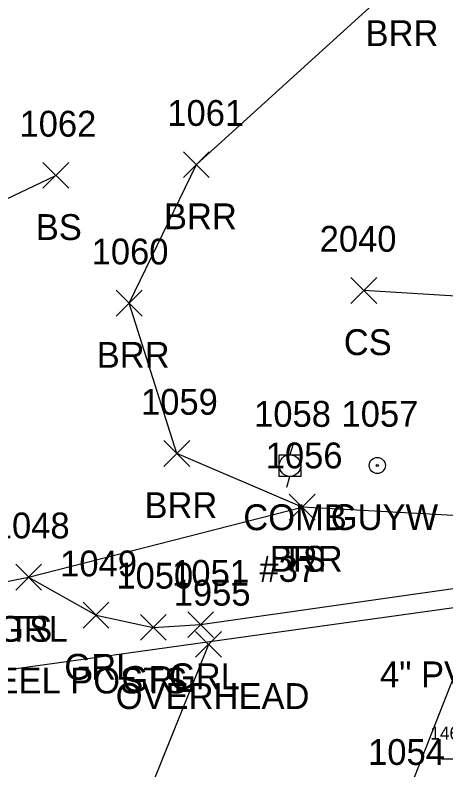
# Model space of a CAD drawing. Extents: x 1600395 to 1603269, y 874955 to 877143.
# Drawn here: x 1601724 to 1601757.4, y 875237.1 to 875295.5 of the extents above; entities that cross this region are included whole.
import ezdxf

# ---------------------------------------------------------------- set-up
doc = ezdxf.new("R2010")
doc.units = 0
for name, color, linetype in [('B_I', 7, 'Continuous'), ('B_TIC', 7, 'Continuous'), ('L_A', 7, 'Continuous'), ('L_I', 7, 'Continuous'), ('L_TIC', 7, 'Continuous'), ('LABL', 7, 'Continuous'), ('LELB', 7, 'Continuous'), ('P_I', 7, 'Continuous'), ('PET', 7, 'Continuous'), ('R_A', 7, 'Continuous'), ('R_C', 7, 'Continuous'), ('R_I', 7, 'Continuous'), ('R_TIC', 7, 'Continuous'), ('RGR', 7, 'Continuous'), ('U_A', 7, 'Continuous'), ('U_C', 7, 'Continuous'), ('U_I', 7, 'Continuous'), ('U_TIC', 7, 'Continuous'), ('UCO', 7, 'Continuous'), ('UP', 7, 'Continuous'), ('UPGW', 7, 'Continuous')]:
    doc.layers.add(name, color=color, linetype=linetype)

msp = doc.modelspace()

# ---------------------------------------------------------------- linework, layer by layer
at = {"layer": 'B_TIC'}
msp.add_lwpolyline([(1601757.063, 875237.938), (1601758.063, 875237.938)], dxfattribs=at)
at = {"layer": 'L_TIC'}
for points in [[(1601737.075, 875282.934), (1601739.075, 875284.934)], [(1601739.075, 875282.934), (1601737.075, 875284.934)], [(1601726.194, 875282.102), (1601728.194, 875284.102)], [(1601728.194, 875282.102), (1601726.194, 875284.102)], [(1601750.052, 875273.194), (1601752.052, 875275.194)], [(1601752.052, 875273.194), (1601750.052, 875275.194)], [(1601731.869, 875272.211), (1601733.869, 875274.211)], [(1601733.869, 875272.211), (1601731.869, 875274.211)], [(1601735.567, 875260.578), (1601737.567, 875262.578)], [(1601737.567, 875260.578), (1601735.567, 875262.578)], [(1601745.273, 875256.428), (1601747.273, 875258.428)], [(1601747.273, 875256.428), (1601745.273, 875258.428)], [(1601745.273, 875256.428), (1601747.273, 875258.428)], [(1601747.273, 875256.428), (1601745.273, 875258.428)], [(1601724.08, 875251.006), (1601726.08, 875253.006)], [(1601726.08, 875251.006), (1601724.08, 875253.006)]]:
    msp.add_lwpolyline(points, dxfattribs=at)
at = {"layer": 'LABL'}
msp.add_lwpolyline([(1601761.25, 875256.599), (1601746.273, 875257.428), (1601736.567, 875261.578), (1601732.869, 875273.211), (1601738.075, 875283.934), (1601753.692, 875298.112), (1601772.592, 875313.657), (1601797.68, 875329.997)], dxfattribs=at)
at = {"layer": 'LELB'}
for points in [[(1601507.847, 875247.89), (1601547.421, 875248.527), (1601578.347, 875245.47), (1601617.951, 875253.676), (1601656.941, 875253.767), (1601694.042, 875267.342), (1601727.194, 875283.102)], [(1601777.022, 875268.044), (1601766.132, 875273.264), (1601751.052, 875274.194)], [(1601507.321, 875231.194), (1601546.9, 875233.686), (1601579.202, 875234.27), (1601621.109, 875236.954), (1601658.665, 875241.356), (1601694.784, 875245.501), (1601700.77, 875248.817), (1601715.033, 875250.029), (1601725.08, 875252.006), (1601746.273, 875257.428)]]:
    msp.add_lwpolyline(points, dxfattribs=at)
at = {"layer": 'PET'}
msp.add_lwpolyline([(1601414.027, 875231.868), (1601447.658, 875227.337), (1601480.387, 875224.741), (1601507.332, 875223.944), (1601546.886, 875225.235), (1601579.482, 875227.318), (1601621.881, 875231.182), (1601659.141, 875235.732), (1601695.513, 875240.663), (1601718.889, 875244.213), (1601760.24, 875249.955), (1601754.149, 875234.472), (1601747.535, 875218.619)], dxfattribs=at)
at = {"layer": 'R_TIC'}
for points in [[(1601724.08, 875251.006), (1601726.08, 875253.006)], [(1601726.08, 875251.006), (1601724.08, 875253.006)], [(1601729.304, 875248.068), (1601731.304, 875250.068)], [(1601731.304, 875248.068), (1601729.304, 875250.068)], [(1601733.736, 875247.121), (1601735.736, 875249.121)], [(1601735.736, 875247.121), (1601733.736, 875249.121)], [(1601737.403, 875247.335), (1601739.403, 875249.335)], [(1601739.403, 875247.335), (1601737.403, 875249.335)]]:
    msp.add_lwpolyline(points, dxfattribs=at)
at = {"layer": 'RGR'}
msp.add_lwpolyline([(1601725.08, 875252.006), (1601730.304, 875249.068), (1601734.736, 875248.121), (1601738.403, 875248.335), (1601761.214, 875251.591)], dxfattribs=at)
at = {"layer": 'U_TIC'}
for points in [[(1601738.016, 875245.802), (1601740.016, 875247.802)], [(1601740.016, 875245.802), (1601738.016, 875247.802)]]:
    msp.add_lwpolyline(points, dxfattribs=at)
at = {"layer": 'UCO'}
msp.add_lwpolyline([(1601739.016, 875246.802), (1601721.199, 875202.682), (1601687.29, 875128.811)], dxfattribs=at)
at = {"layer": 'UP'}
for p, q in [((1601745.573, 875262.309), (1601745.323, 875261.476)), ((1601744.489, 875259.809), (1601744.489, 875261.476)), ((1601744.489, 875261.476), (1601746.156, 875261.476)), ((1601746.156, 875261.476), (1601746.156, 875259.809)), ((1601745.323, 875260.643), (1601745.323, 875260.643)), ((1601746.156, 875259.809), (1601744.489, 875259.809)), ((1601745.073, 875258.976), (1601745.323, 875259.809))]:
    msp.add_line(p, q, dxfattribs=at)
msp.add_circle((1601745.323, 875260.643), 0.833, dxfattribs=at)
at = {"layer": 'UPGW'}
for radius in [0.625, 0.0833]:
    msp.add_circle((1601752.09, 875260.65), radius, dxfattribs=at)

# ---------------------------------------------------------------- texts
at = {"layer": 'B_I'}
msp.add_text('1468', height=1, dxfattribs=at).set_placement((1601756.193, 875239.438))
at = {"layer": 'L_A'}
for s, p in [('BRR', (1601751.18, 875293.112)), ('BRR', (1601735.564, 875278.934)), ('BS', (1601725.635, 875278.102)), ('CS', (1601749.493, 875269.194)), ('BRR', (1601730.357, 875268.211)), ('BRR', (1601734.055, 875256.578)), ('BRR', (1601743.761, 875252.428)), ('TS', (1601744.682, 875252.428)), ('TS', (1601723.489, 875247.006))]:
    msp.add_text(s, height=2, dxfattribs=at).set_placement(p)
at = {"layer": 'L_I'}
for s, p in [('1061', (1601735.824, 875286.934)), ('1062', (1601724.375, 875286.102)), ('2040', (1601747.626, 875277.194)), ('1060', (1601729.963, 875276.211)), ('1059', (1601733.788, 875264.578)), ('1056', (1601743.446, 875260.428)), ('1056', (1601743.446, 875260.428)), ('1048', (1601722.308, 875255.006))]:
    msp.add_text(s, height=2, dxfattribs=at).set_placement(p)
at = {"layer": 'P_I'}
msp.add_text('1054', height=2, dxfattribs=at).set_placement((1601751.378, 875237.472))
msp.add_text('1054', height=2, dxfattribs=at).set_placement((1601751.378, 875237.472))
at = {"layer": 'R_A'}
for p in [(1601722.623, 875247.006), (1601727.848, 875244.068), (1601732.279, 875243.121), (1601735.947, 875243.335)]:
    msp.add_text('GRL', height=2, dxfattribs=at).set_placement(p)
at = {"layer": 'R_C'}
msp.add_text('SGR W/STEEL POSTS', height=2, dxfattribs=at).set_placement((1601709.285, 875243.006))
at = {"layer": 'R_I'}
for s, p in [('1048', (1601722.308, 875255.006)), ('1049', (1601727.525, 875252.068)), ('1050', (1601731.878, 875251.121)), ('1051', (1601736.199, 875251.335))]:
    msp.add_text(s, height=2, dxfattribs=at).set_placement(p)
at = {"layer": 'U_A'}
for s, p in [('COMB', (1601741.709, 875255.643)), ('GUYW', (1601748.483, 875255.65)), ('OVERHEAD', (1601731.827, 875241.802))]:
    msp.add_text(s, height=2, dxfattribs=at).set_placement(p)
at = {"layer": 'U_C'}
for s, p in [('#37', (1601742.961, 875251.643)), ('4" PVC CONDUIT', (1601752.3, 875243.481))]:
    msp.add_text(s, height=2, dxfattribs=at).set_placement(p)
at = {"layer": 'U_I'}
for s, p in [('1058', (1601742.551, 875263.643)), ('1057', (1601749.318, 875263.65)), ('1955', (1601736.323, 875249.802))]:
    msp.add_text(s, height=2, dxfattribs=at).set_placement(p)

doc.saveas('drawing.dxf')
